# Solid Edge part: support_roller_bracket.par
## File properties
Title: Support roller bracket
Author: Abhinav Rai
Template: Normal.par
Last saved by: CADCIM
Revision: 16
Application: Solid Edge
Material: aluminum
Density: 0 kg/mm^3
Accuracy: 0.99
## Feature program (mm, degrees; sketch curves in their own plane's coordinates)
sketch for "unnamed Protrusion 1" #1 plane through (0, 0, 0) normal (0, -1, 0) x-axis (1, 0, 0)
  circle centre (0, -138.9237) radius 3.81
sketch for "unnamed Protrusion 1" #2 plane through (0, 0, 0) normal (0, -1, 0) x-axis (1, 0, 0)
  line (143.637, -99.9249) -> (-143.637, -99.9249)
  line (-143.637, -99.9249) -> (-143.637, -115.1647)
  line (-143.637, -115.1647) -> (-61.0846, -156.7704)
  line (-61.0846, -156.7704) -> (-61.0846, -162.9363)
  line (-61.0846, -162.9363) -> (61.0846, -162.9363)
  line (61.0846, -156.7704) -> (61.0846, -162.9363)
  line (143.637, -115.1647) -> (61.0846, -156.7704)
  line (143.637, -99.9249) -> (143.637, -115.1647)
  dimension (linear) = 143.637
extrude "unnamed Protrusion 1" add finite 101.6 symmetric
fillet "Round_1" radius 31.75
fillet "Round_2" radius 6.35
sketch for "unnamed Protrusion 2" plane through (0, 0, 67.2512) normal (1, 0, 0) x-axis (0, 1, 0)
  arc centre (-23.4135, -61.792) radius 19.05 from (-23.4135, -42.742) to (-42.405, -60.3002) ccw
  line (-50.8, -167.1761) -> (-42.405, -60.3002)
  line (-50.8, -167.1761) -> (50.8, -167.1761)
  line (45.7777, -60.8928) -> (50.8, -167.1761)
  arc centre (26.749, -61.792) radius 19.05 from (26.749, -42.742) to (45.7777, -60.8928) cw
  line (19.05, -42.742) -> (26.749, -42.742)
  line (19.05, -64.967) -> (19.05, -42.742)
  arc centre (0, -64.967) radius 19.05 from (-19.05, -64.967) to (19.05, -64.967) ccw
  line (-19.05, -42.742) -> (-19.05, -64.967)
  line (-23.4135, -42.742) -> (-19.05, -42.742)
extrude "unnamed Protrusion 2" add to key point symmetric
sketch for "ExtrudedCutout_1" plane through (0, 0, 0) normal (0, -1, 0) x-axis (1, 0, 0)
  line (-128.3193, 24.5092) -> (125.6319, 24.5092)
  line (125.6319, 24.5092) -> (125.6319, -99.9249)
  line (125.6319, -99.9249) -> (-128.3193, -99.9249)
  line (-128.3193, -99.9249) -> (-128.3193, 24.5092)
extrude "ExtrudedCutout_1" cut finite 203.2 symmetric
chamfer "Chamfer_1" setback 5.08
rib "Rib_1"  Thickness = 25.4 mm
mirror "unnamed Mirror 1" of "Rib_1" about plane through (0, 0, 0) normal (1, 0, 0)
rib "unnamed Rib 1"
sketch for "Hole_1" plane through (0.1259, 0, -162.9363) normal (0, 0, -1) x-axis (-1, 0, 0)
  hole centre (0.1259, 0) bore radius 25.4
hole "Hole_1" diameter 50.8 through
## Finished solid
Body 1: solid body, 55 faces, 142 edges, 86 vertices.
  Faces by surface: plane 38, cylinder 17
  Edges by curve: line 106, circle 34, intersection 2
Bounding box of the edges (mm): 379.121 x 101.600 x 187.446, from (-189.5605, -50.8, -162.9363) to (189.5605, 50.8, 24.5092).
Cylindrical faces by radius (mm): R3.81 x2, R6.35 x2, R19.05 x6, R25.4 x1, R31.75 x4, R55.372 x2
Planar faces by outward normal: +x 4, +y 5, +z 5, -x 4, -y 5, -z 1, oblique 14
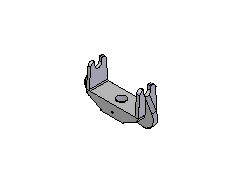
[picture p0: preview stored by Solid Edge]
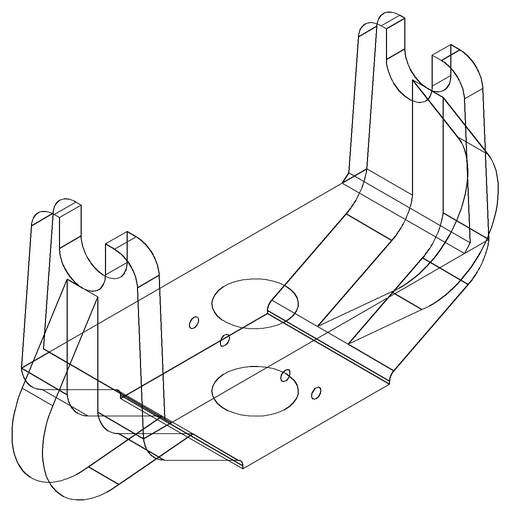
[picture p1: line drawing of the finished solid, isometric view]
